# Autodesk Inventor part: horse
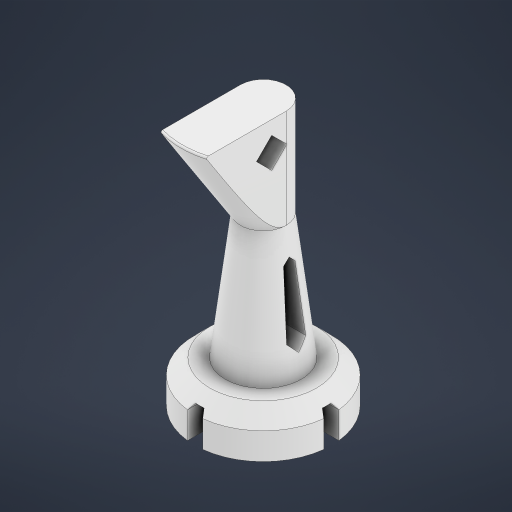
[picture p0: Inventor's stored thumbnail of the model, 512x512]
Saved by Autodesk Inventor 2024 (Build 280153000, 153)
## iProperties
Created: 2025-07
Part Number: horse
Material: ABS Plastic
Document SubType Name: Modeling
Designer: acer
Density: 1.06 g/cm^3
Appearance: Smooth - White
Author: acer
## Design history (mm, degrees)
sketch "Sketch1"
  geometry: L1 (0, 0)-(0, 9); L2 (0, 9)-(5.5, 9); L3 (0, 0)-(35, 0); L4 (5.5, 9)-(5.5, 5); L5 (0, 0)-(22, 0); L6 (22, 0)-(22, 3); L7 (22, 3)-(5.5, 5); L8 (35, 0)-(35, 11); L9 (35, 11)-(22, 3)
  constraints: 18 end point, 3 vertical, 2 horizontal, 1 perpendicular, 1 point on line
  dimensions: "d0" = 9 distance of L1.start L1.end; "d1" = 5.5 distance of L1.end L2.end; "d2" = 35 distance of L1.start L3.end; "d3" = 4 distance of L2.end L4.end; "d4" = 22 distance of L1.start L5.end; "d5" = 3 distance of L5.end L6.end; "d6" = 11 distance of L3.end L8.end
revolve "Revolution1" sketch "Sketch1" stored, may be unused: angle "d7" = 90 deg
sketch "Sketch2"
  geometry: L1 (22, -3)-(22, 3) reference; L2 (22, 0)-(42.639, 0); L3 (42.639, 0)-(42.639, -13.795); L4 (42.639, -13.795)-(22, -13.795); L5 (22, -13.795)-(22, 0); 2 further points
  constraints: 8 end point, 2 parallel, 1 horizontal, 1 midpoint, 1 perpendicular
extrude "Extrusion1" cut sketch "Sketch2" distance "d8" = 16.25; taper "d10" = 0 deg; dims "d9" = 15.25, "d11" = 0
sketch "Sketch3"
  geometry: L1 (14, -13)-(8, -13) reference; L2 (8, -13)-(-3.84, -13); L3 (-3.84, -13)-(-3.84, 6.664); L4 (-3.84, 6.664)-(8, 6.664); L5 (8, 6.664)-(8, -13); L6 (14, -13)-(25.143, -13); L7 (25.143, -13)-(25.143, 7.918); L8 (25.143, 7.918)-(14, 7.918); L9 (14, 7.918)-(14, -13); 1 further point
  constraints: 16 end point, 4 parallel, 2 horizontal, 2 perpendicular
extrude "Extrusion2" cut sketch "Sketch3" distance "d12" = 16.5; taper "d13" = 0 deg
sketch "Sketch4"
  geometry: L1 (-3, 0)-(3, 0) reference; 3 further points
  constraints: 1 coincident, 3 other
extrude "Extrusion3" join sketch "Sketch4" stored distance "d14" = 16.5; taper "d15" = 0 deg
chamfer "Chamfer1" distance "d16" = 2; stored, may be unused: second distance "d17" = 2, angle "d18" = 45 deg
sketch "Sketch5"
  geometry: L1 (-1.891, 7.199)-(-3.891, 9.199); L2 (-3.891, 9.199)-(-1.891, 11.199); L3 (-1.891, 11.199)-(0.109, 9.199); L4 (0.109, 9.199)-(-1.891, 7.199); A1 r 2 centre (-1.891, 9.199) between (-1.891, 7.199) and (-3.891, 9.199); 1 further point
  constraints: 8 end point, 4 point on circle, 3 perpendicular, 1 centre point
  dimensions: "d19" = 4 diameter of A1
extrude "Extrusion4" cut sketch "Sketch5" distance "d20" = 6.75; taper "d22" = 0 deg; dims "d21" = 8.375, "d23" = 0
fillet "Fillet1" dims "d24" = 0.2
sketch "Sketch6"
  geometry: L1 (5.5, -5)-(5.5, 5) reference; L2 (-5.5, 1)-(5.5, 1); L3 (5.5, 1)-(5.5, -1); L4 (5.5, -1)-(-5.5, -1); L5 (-5.5, -1)-(-5.5, 1); L6 (-5.5, 1)-(5.5, -1); L7 (5.5, 1)-(-5.5, -1); L8 (3.5, -9)-(3.5, 9) reference; L9 (5.5, 0)-(5, 0); L10 (5, 0)-(3.5, 1); L11 (5, 0)-(3.5, -1); 1 further point
  constraints: 18 end point, 5 point on line, 3 midpoint, 2 horizontal, 2 parallel, 1 perpendicular
  dimensions: "d25" = 2 distance of L2.end L3.end; "d28" = 0.5 distance of L9.start L9.end
extrude "Extrusion6" cut sketch "Sketch6" stored distance "d29" = 26.25; taper "d30" = 0 deg
chamfer "Chamfer2" distance "d31" = 1; stored, may be unused: second distance "d32" = 2, angle "d33" = 45 deg
sketch "Sketch7"
  geometry: L1 (5, 5.5)-(-5, 5.5) reference; L2 (-1, -5.5)-(1, -5.5); L3 (1, -5.5)-(1, 5.5); L4 (1, 5.5)-(-1, 5.5); L5 (-1, 5.5)-(-1, -5.5); L6 (-1, -5.5)-(1, 5.5); L7 (1, -5.5)-(-1, 5.5); L8 (0, 5.5)-(0, 5); L9 (0, 5)-(-1, 3.5); L10 (-8.944, 3.5)-(8.944, 3.5) reference; L11 (0, 5)-(1, 3.5); 1 further point
  constraints: 18 end point, 5 point on line, 3 midpoint, 2 parallel, 1 horizontal, 1 perpendicular, 1 vertical
  dimensions: "d34" = 2 distance of L4.end L3.end; "d35" = 0.5 distance of L8.start L8.end
extrude "Extrusion7" cut sketch "Sketch7" stored distance "d36" = 26.25; taper "d37" = 0 deg
chamfer "Chamfer3" distance "d38" = 1; stored, may be unused: second distance "d39" = 2, angle "d40" = 45 deg
sketch "Sketch8"
  geometry: L1 (22, -3)-(22, 0) reference; L2 (22, 0)-(5.5, 0); L3 (5.5, 7)-(5.5, -7) reference; L4 (5.5, 0)-(9.625, 0); L5 (9.625, 0)-(13.75, 0); L6 (13.75, 0)-(17.875, 0); L7 (17.92, 0.749)-(18.625, 0); L8 (18.625, 0)-(17.83, -0.749); L9 (8.375, 0)-(9.549, -1.248); L10 (8.375, 0)-(9.701, 1.248); L11 (9.701, 1.248)-(17.92, 0.749); L12 (9.549, -1.248)-(17.83, -0.749); A1 r 1.25 centre (9.625, 0) between (8.375, 0) and (9.549, -1.248); A2 r 0.75 centre (17.875, 0) between (17.92, 0.749) and (18.625, 0); 1 further point
  constraints: 20 end point, 6 point on circle, 4 point on line, 3 perpendicular, 2 centre point, 2 coincident, 2 midpoint, 1 tangent
  dimensions: "d41" = 4.125 distance of L2.end L4.end; "d42" = 4.125 distance of L5.end L6.end; "d43" = 2.5 diameter of A1; "d44" = 1.5 diameter of A2
extrude "Extrusion8" cut sketch "Sketch8" stored distance "d45" = 26.25; taper "d46" = 0 deg
body "Solid1"
